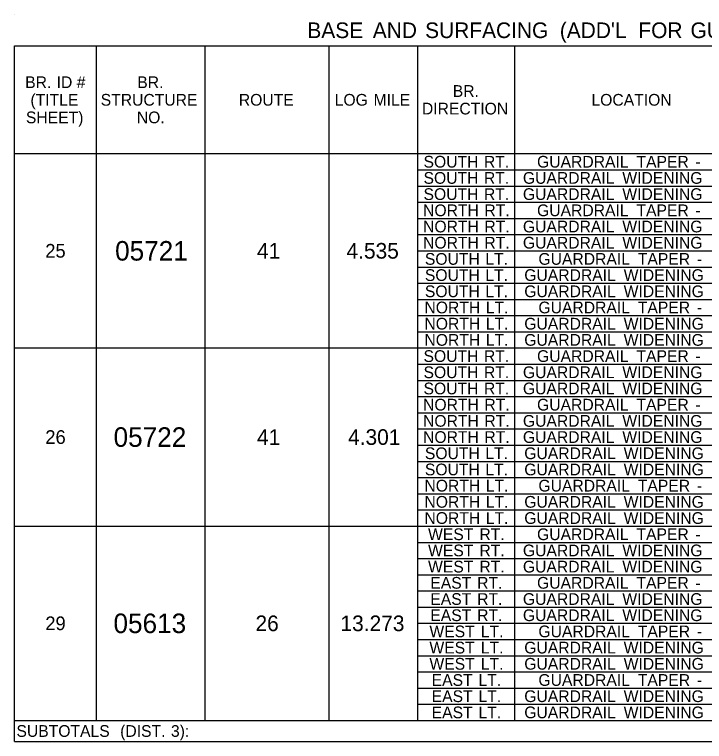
# Model space of a CAD drawing. Extents: x 544250 to 1930787, y -1948365 to 596640.
# Drawn here: x 558321.6 to 558674.5, y -1946614.5 to -1946242.5 of the extents above; entities that cross this region are included whole.
import ezdxf

# ---------------------------------------------------------------- set-up
doc = ezdxf.new("R2010")
doc.units = 0
doc.layers.add('Default', color=7, linetype='Continuous')

msp = doc.modelspace()

# ---------------------------------------------------------------- linework, layer by layer
at = {"layer": 'Default'}
for p, q in [((558321.63, -1946242.54), (558321.63, -1946242.54)), ((558321.63, -1946258.62), (559004.62, -1946258.62)), ((558321.63, -1946614.5), (558321.63, -1946258.62)), ((558363.55, -1946603.77), (558363.55, -1946258.62)), ((558419.13, -1946603.77), (558419.13, -1946258.62)), ((558482.5, -1946603.77), (558482.5, -1946258.62)), ((558527.84, -1946603.77), (558527.84, -1946258.62)), ((558577.57, -1946603.77), (558577.57, -1946258.62)), ((558321.63, -1946313.71), (559004.62, -1946313.71)), ((558527.84, -1946322), (559004.62, -1946322)), ((558527.84, -1946330.29), (559004.62, -1946330.29)), ((558527.84, -1946338.57), (559004.62, -1946338.57)), ((558527.84, -1946346.86), (559004.62, -1946346.86)), ((558527.84, -1946355.15), (559004.62, -1946355.15)), ((558527.84, -1946363.44), (559004.62, -1946363.44)), ((558527.84, -1946371.72), (559004.62, -1946371.72)), ((558527.84, -1946380.01), (559004.62, -1946380.01)), ((558527.84, -1946388.3), (559004.62, -1946388.3)), ((558527.84, -1946396.59), (559004.62, -1946396.59)), ((558527.84, -1946404.87), (559004.62, -1946404.87)), ((558321.63, -1946413.16), (559004.62, -1946413.16)), ((558527.84, -1946421.45), (559004.62, -1946421.45)), ((558527.84, -1946429.74), (559004.62, -1946429.74)), ((558527.84, -1946438.02), (559004.62, -1946438.02)), ((558527.84, -1946446.31), (559004.62, -1946446.31)), ((558527.84, -1946454.6), (559004.62, -1946454.6)), ((558527.84, -1946462.89), (559004.62, -1946462.89)), ((558527.84, -1946471.17), (559004.62, -1946471.17)), ((558527.84, -1946479.46), (559004.62, -1946479.46)), ((558527.84, -1946487.75), (559004.62, -1946487.75)), ((558527.84, -1946496.04), (559004.62, -1946496.04)), ((558321.63, -1946504.32), (559004.62, -1946504.32)), ((558527.84, -1946512.61), (559004.62, -1946512.61)), ((558527.84, -1946520.9), (559004.62, -1946520.9)), ((558527.84, -1946529.19), (559004.62, -1946529.19)), ((558527.84, -1946537.47), (559004.62, -1946537.47)), ((558527.84, -1946545.76), (559004.62, -1946545.76)), ((558527.84, -1946554.05), (559004.62, -1946554.05)), ((558527.84, -1946562.34), (559004.62, -1946562.34)), ((558527.84, -1946570.62), (559004.62, -1946570.62)), ((558527.84, -1946578.91), (559004.62, -1946578.91)), ((558527.84, -1946587.2), (559004.62, -1946587.2)), ((558527.84, -1946595.49), (559004.62, -1946595.49)), ((558321.63, -1946603.77), (559004.62, -1946603.77)), ((558321.63, -1946614.5), (559004.62, -1946614.5))]:
    msp.add_line(p, q, dxfattribs=at)

# ---------------------------------------------------------------- texts
for s, height, p in [('BASE', 8, (558471.4, -1946254.58)), (' AND', 8, (558501.9, -1946254.58)), (' SURFACING', 8, (558528.67, -1946254.58)), (" (ADD'L", 8, (558597.55, -1946254.58)), (' FOR', 8, (558637.74, -1946254.58)), (' GUARDRAIL)', 8, (558664.39, -1946254.58)), ('BR.', 6, (558327.07, -1946280.17)), (' ID', 6, (558340.93, -1946280.17)), (' #', 6, (558351.22, -1946280.17)), ('BR.', 6, (558384.41, -1946280.17)), ('BR.', 6, (558545.77, -1946284.67)), ('(TITLE', 6, (558329.76, -1946289.17)), ('STRUCTURE', 6, (558365.7, -1946289.17)), ('ROUTE', 6, (558436.35, -1946289.17)), ('LOG', 6, (558485.38, -1946289.17)), (' MILE', 6, (558503.03, -1946289.17)), ('LOCATION', 6, (558616.71, -1946289.17)), ('DIRECTION', 6, (558529.98, -1946293.67)), ('SHEET)', 6, (558327.44, -1946298.17)), ('NO.', 6, (558384.18, -1946298.17)), ('SOUTH', 6, (558530.82, -1946320.86)), (' RT.', 6, (558559.49, -1946320.86)), ('GUARDRAIL', 6, (558588.89, -1946320.86)), (' TAPER', 6, (558637.51, -1946320.86)), (' -', 6, (558667.67, -1946320.86)), ('SOUTH', 6, (558530.82, -1946329.14)), (' RT.', 6, (558559.49, -1946329.14)), ('GUARDRAIL', 6, (558581.65, -1946329.14)), (' WIDENING', 6, (558630.27, -1946329.14)), ('SOUTH', 6, (558530.82, -1946337.43)), (' RT.', 6, (558559.49, -1946337.43)), ('GUARDRAIL', 6, (558581.65, -1946337.43)), (' WIDENING', 6, (558630.27, -1946337.43)), ('NORTH', 6, (558530.59, -1946345.72)), (' RT.', 6, (558559.72, -1946345.72)), ('GUARDRAIL', 6, (558588.89, -1946345.72)), (' TAPER', 6, (558637.51, -1946345.72)), (' -', 6, (558667.67, -1946345.72)), ('NORTH', 6, (558530.59, -1946354.01)), (' RT.', 6, (558559.72, -1946354.01)), ('GUARDRAIL', 6, (558581.65, -1946354.01)), (' WIDENING', 6, (558630.27, -1946354.01)), ('NORTH', 6, (558530.59, -1946362.29)), (' RT.', 6, (558559.72, -1946362.29)), ('GUARDRAIL', 6, (558581.65, -1946362.29)), (' WIDENING', 6, (558630.27, -1946362.29)), ('25', 7, (558337.35, -1946366.94)), ('05721', 10, (558373.06, -1946368.44)), ('41', 8, (558445.63, -1946367.44)), ('4.535', 8, (558491.42, -1946367.44)), ('SOUTH', 6, (558531.52, -1946370.58)), (' LT.', 6, (558560.19, -1946370.58)), ('GUARDRAIL', 6, (558589.59, -1946370.58)), (' TAPER', 6, (558638.2, -1946370.58)), (' -', 6, (558668.37, -1946370.58)), ('SOUTH', 6, (558531.52, -1946378.87)), (' LT.', 6, (558560.19, -1946378.87)), ('GUARDRAIL', 6, (558582.35, -1946378.87)), (' WIDENING', 6, (558630.96, -1946378.87)), ('SOUTH', 6, (558531.52, -1946387.16)), (' LT.', 6, (558560.19, -1946387.16)), ('GUARDRAIL', 6, (558582.35, -1946387.16)), (' WIDENING', 6, (558630.96, -1946387.16)), ('NORTH', 6, (558531.29, -1946395.44)), (' LT.', 6, (558560.42, -1946395.44)), ('GUARDRAIL', 6, (558589.59, -1946395.44)), (' TAPER', 6, (558638.2, -1946395.44)), (' -', 6, (558668.37, -1946395.44)), ('NORTH', 6, (558531.29, -1946403.73)), (' LT.', 6, (558560.42, -1946403.73)), ('GUARDRAIL', 6, (558582.35, -1946403.73)), (' WIDENING', 6, (558630.96, -1946403.73)), ('NORTH', 6, (558531.29, -1946412.02)), (' LT.', 6, (558560.42, -1946412.02)), ('GUARDRAIL', 6, (558582.35, -1946412.02)), (' WIDENING', 6, (558630.96, -1946412.02)), ('SOUTH', 6, (558530.82, -1946420.31)), (' RT.', 6, (558559.49, -1946420.31)), ('GUARDRAIL', 6, (558588.89, -1946420.31)), (' TAPER', 6, (558637.51, -1946420.31)), (' -', 6, (558667.67, -1946420.31)), ('SOUTH', 6, (558530.82, -1946428.59)), (' RT.', 6, (558559.49, -1946428.59)), ('GUARDRAIL', 6, (558581.65, -1946428.59)), (' WIDENING', 6, (558630.27, -1946428.59)), ('SOUTH', 6, (558530.82, -1946436.88)), (' RT.', 6, (558559.49, -1946436.88)), ('GUARDRAIL', 6, (558581.65, -1946436.88)), (' WIDENING', 6, (558630.27, -1946436.88)), ('NORTH', 6, (558530.59, -1946445.17)), (' RT.', 6, (558559.72, -1946445.17)), ('GUARDRAIL', 6, (558588.89, -1946445.17)), (' TAPER', 6, (558637.51, -1946445.17)), (' -', 6, (558667.67, -1946445.17)), ('NORTH', 6, (558530.59, -1946453.46)), (' RT.', 6, (558559.72, -1946453.46)), ('GUARDRAIL', 6, (558581.65, -1946453.46)), (' WIDENING', 6, (558630.27, -1946453.46)), ('05722', 10, (558372.28, -1946463.74)), ('26', 7, (558337.38, -1946462.24)), ('41', 8, (558445.63, -1946462.74)), ('4.301', 8, (558492.22, -1946462.74)), ('NORTH', 6, (558530.59, -1946461.74)), (' RT.', 6, (558559.72, -1946461.74)), ('GUARDRAIL', 6, (558581.65, -1946461.74)), (' WIDENING', 6, (558630.27, -1946461.74)), ('SOUTH', 6, (558531.52, -1946470.03)), (' LT.', 6, (558560.19, -1946470.03)), ('GUARDRAIL', 6, (558582.35, -1946470.03)), (' WIDENING', 6, (558630.96, -1946470.03)), ('SOUTH', 6, (558531.52, -1946478.32)), (' LT.', 6, (558560.19, -1946478.32)), ('GUARDRAIL', 6, (558582.35, -1946478.32)), (' WIDENING', 6, (558630.96, -1946478.32)), ('NORTH', 6, (558531.29, -1946486.61)), (' LT.', 6, (558560.42, -1946486.61)), ('GUARDRAIL', 6, (558589.59, -1946486.61)), (' TAPER', 6, (558638.2, -1946486.61)), (' -', 6, (558668.37, -1946486.61)), ('NORTH', 6, (558531.29, -1946494.89)), (' LT.', 6, (558560.42, -1946494.89)), ('GUARDRAIL', 6, (558582.35, -1946494.89)), (' WIDENING', 6, (558630.96, -1946494.89)), ('NORTH', 6, (558531.29, -1946503.18)), (' LT.', 6, (558560.42, -1946503.18)), ('GUARDRAIL', 6, (558582.35, -1946503.18)), (' WIDENING', 6, (558630.96, -1946503.18)), ('WEST', 6, (558533.13, -1946511.47)), (' RT.', 6, (558557.18, -1946511.47)), ('GUARDRAIL', 6, (558588.89, -1946511.47)), (' TAPER', 6, (558637.51, -1946511.47)), (' -', 6, (558667.67, -1946511.47)), ('WEST', 6, (558533.13, -1946519.76)), (' RT.', 6, (558557.18, -1946519.76)), ('GUARDRAIL', 6, (558581.65, -1946519.76)), (' WIDENING', 6, (558630.27, -1946519.76)), ('WEST', 6, (558533.13, -1946528.04)), (' RT.', 6, (558557.18, -1946528.04)), ('GUARDRAIL', 6, (558581.65, -1946528.04)), (' WIDENING', 6, (558630.27, -1946528.04)), ('EAST', 6, (558534.29, -1946536.33)), (' RT.', 6, (558556.02, -1946536.33)), ('GUARDRAIL', 6, (558588.89, -1946536.33)), (' TAPER', 6, (558637.51, -1946536.33)), (' -', 6, (558667.67, -1946536.33)), ('EAST', 6, (558534.29, -1946544.62)), (' RT.', 6, (558556.02, -1946544.62)), ('GUARDRAIL', 6, (558581.65, -1946544.62)), (' WIDENING', 6, (558630.27, -1946544.62)), ('05613', 10, (558372.23, -1946559.05)), ('26', 8, (558444.86, -1946558.05)), ('13.273', 8, (558488.34, -1946558.05)), ('EAST', 6, (558534.29, -1946552.91)), (' RT.', 6, (558556.02, -1946552.91)), ('GUARDRAIL', 6, (558581.65, -1946552.91)), (' WIDENING', 6, (558630.27, -1946552.91)), ('29', 7, (558337.37, -1946557.55)), ('WEST', 6, (558533.83, -1946561.19)), (' LT.', 6, (558557.88, -1946561.19)), ('GUARDRAIL', 6, (558589.59, -1946561.19)), (' TAPER', 6, (558638.2, -1946561.19)), (' -', 6, (558668.37, -1946561.19)), ('WEST', 6, (558533.83, -1946569.48)), (' LT.', 6, (558557.88, -1946569.48)), ('GUARDRAIL', 6, (558582.35, -1946569.48)), (' WIDENING', 6, (558630.96, -1946569.48)), ('WEST', 6, (558533.83, -1946577.77)), (' LT.', 6, (558557.88, -1946577.77)), ('GUARDRAIL', 6, (558582.35, -1946577.77)), (' WIDENING', 6, (558630.96, -1946577.77)), ('EAST', 6, (558534.99, -1946586.06)), (' LT.', 6, (558556.72, -1946586.06)), ('GUARDRAIL', 6, (558589.59, -1946586.06)), (' TAPER', 6, (558638.2, -1946586.06)), (' -', 6, (558668.37, -1946586.06)), ('EAST', 6, (558534.99, -1946594.34)), (' LT.', 6, (558556.72, -1946594.34)), ('GUARDRAIL', 6, (558582.35, -1946594.34)), (' WIDENING', 6, (558630.96, -1946594.34)), ('EAST', 6, (558534.99, -1946602.63)), (' LT.', 6, (558556.72, -1946602.63)), ('GUARDRAIL', 6, (558582.35, -1946602.63)), (' WIDENING', 6, (558630.96, -1946602.63)), ('SUBTOTALS', 6, (558322.6, -1946612.14)), (' (DIST.', 6, (558373.43, -1946612.14)), (' 3):', 6, (558399.4, -1946612.14))]:
    msp.add_text(s, height=height, dxfattribs=at).set_placement(p)

doc.saveas('drawing.dxf')
